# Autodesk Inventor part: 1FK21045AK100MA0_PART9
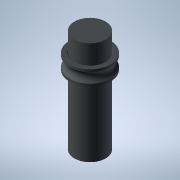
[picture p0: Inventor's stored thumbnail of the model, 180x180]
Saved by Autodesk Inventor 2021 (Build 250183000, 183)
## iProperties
Created: 2025-04
Part Number: 1FK21045AK100MA0_PART9
Material: Generic
Catalog Web Link: www.3dfindit.com
Description: -Servo synchronous motor
Document SubType Name: Modeling
Designer: psAdmin
Mass: 18.6788 g
Surface Area: 52.316 cm^2
Volume: 18.6788 cm^3
Density: 1 g/cm^3
Appearance: PSOLRGB-212-217-219
Category: PARTsolutions
Title: 1FK21045AK100MA0_PART9
Author: Cadenas PARTsolutions
Comments: Servo synchronous motor
Sending System: PARTsolutions
Preprocessor: ST-DEVELOPER v19.3
PSOL_IDENT_0: {$CADENAS_DATA/23d-libs/siemens_ag/_cat_/e0/5f/1fk21045ak100ma0.prj},213 {VTYP=3D},{NB=1FK21045AK100
PSOL_IDENT_1: MA0_PART9},{LINA=1FK21045AK100MA0_PART9},{NN=1FK21045AK100MA0_PART9},{NOPRJ=TRUE},{DATE=19.08.2025 1
PSOL_IDENT_2: 4:01:03},{GEOMDATE=30.07.2025 02:01:57},{VERSION=},{LINEID=10},{WBVAR=},{WBNUMERIC=}  {NB=1FK21045AK
PSOL_IDENT_3: 100MA0_PART9},{LINA=1FK21045AK100MA0_PART9},{KT=DUMMY},{PREVIEW=../../../_pool_/0f/2c/p_d211_xx_0043
PSOL_IDENT_4: 8j.png},{DESCSHORT=SIMOTICS S-1FK2 HD, SINAMICS S210 3AC 400V-480V, 1.7 Nm, 6000 rpm},{DESCLONG=SIMO
PSOL_IDENT_5: TICS S-1FK2 HD servo motor M0=2.4 Nm; PN = 1.07 kW at nN=6000 rpm (380-480 V); PN = 0.75 kW at nN=30
PSOL_IDENT_6: 00 rpm (200-240 V); with holding brake; degree of protection IP64; cylindrical shaft D19x40mm; absol
PSOL_IDENT_7: ute encoder 22-bit + 12-bit multiturn (encoder AM22DQC); with OCC interface; plug size M17, rotatabl
PSOL_IDENT_8: e; SIMOTICS S-1FK2 servomotorfor a wide range of uses in industrial environments. SIMOTICS S‑1FK2 se
PSOL_IDENT_9: rvomotors are compact synchronous motors with a high dynamic performance that set themselves apart a
PSOL_IDENT_10: s a result of their high power density, degree of protection and overload capability. The motors are
PSOL_IDENT_11: available in two variants: as High Dynamic variant (highest dynamic performance as a result of the
PSOL_IDENT_12: low intrinsic moment of inertia for applications demanding a high dynamic performance with low moved
PSOL_IDENT_13: masses) - and as Compact variant (precise and stable closed-loop control for medium up to large mov
PSOL_IDENT_14: ed masses as a result of a medium intrinsic moment of inertia). SIMOTICSS‑1FK2 servomotors fully exp
PSOL_IDENT_15: loit their strengths in a system with the SINAMICSS210 frequency converter and simple connection usi
PSOL_IDENT_16: ng the one cable connection (OCC). Advantages include the short control and positioning times, fast
PSOL_IDENT_17: and precise correction of disturbing quantities as well as stable control with a high dynamic perfor
PSOL_IDENT_18: mance. The servo motors can be configured to address a wide range of requirements. For example with
PSOL_IDENT_19: and without holding brake, IP64 or IP65 degree of protection, singleturn or multiturn absolute encod
PSOL_IDENT_20: ers - to name just a few. Further, the servomotors are available in different shaft heights extendin
PSOL_IDENT_21: g from 20 to 100. A shaft sealing ring is available to achieve an IP65 degree of protection and for
PSOL_IDENT_22: subsequent mounting at the motor or as spare part. SIMOTICS - the optimum motor for each and every m
PSOL_IDENT_23: otion control application.},{INTNO=804766807114},{SUPPLIERALTNO=1FK2104-5AK10-0MA0},{MANUID=1FK21045
PSOL_IDENT_24: AK100MA0},{MANUNAME=Siemens},{MANUTYPEDESC=Synchronous motor 1FK2-HD 2,39 Nm},{AAU732=SIMOTICS},{AAO
PSOL_IDENT_25: 057=S-1FK2},{AAU734=SIMOTICS S-1FK2 HD servo motor M0=2.4 Nm; PN = 1.07 kW at nN=6000 rpm (380-480 V
PSOL_IDENT_26: ); PN = 0.75 kW at nN=3000 rpm (200-240 V); with holding brake; degree of protection IP64; cylindric
PSOL_IDENT_27: al shaft D19x40mm; absolute encoder 22-bit + 12-bit multiturn (encoder AM22DQC); with OCC interface;
PSOL_IDENT_28: plug size M17, rotatable;},{AAW338=Synchronous motor 1FK2-HD 2,39 Nm},{AAO742=SIMOTICS},{AAO663=404
PSOL_IDENT_29: 2948691236},{NOCUPEROU=1},{PRICEQUANTITY=1},{QUANTITYMIN=1},{QUANTITYINT=1},{CTN=85015100},{COO=DE},
PSOL_IDENT_30: {AAO676=1FK2104-5AK10-0MA0},{AAO677=Siemens AG},{ORDERUNIT=C62},{CONTENTUNIT=C62}
NB: 1FK21045AK100MA0_PART9
NT: Servo synchronous motor
NBSYN: $MANUID._PART9
LINA: 1FK21045AK100MA0_PART9
CATALOG: SIEMENS
PREVIEW: ../../../_pool_/0f/2c/p_d211_xx_00438j.png
DESCSHORT: SIMOTICS S-1FK2 HD, SINAMICS S210 3AC 400V-480V, 1.7 Nm, 6000 rpm
DESCLONG: SIMOTICS S-1FK2 HD servo motor M0=2.4 Nm; PN = 1.07 kW at nN=6000 rpm (380-480 V); PN = 0.75 kW at nN=3000 rpm (200-240 V); with holding brake; degree of protec
INTNO: 804766807114
SUPPLIERALTNO: 1FK2104-5AK10-0MA0
MANUID: 1FK21045AK100MA0
MANUNAME: Siemens
MANUTYPEDESC: Synchronous motor 1FK2-HD 2,39 Nm
AAU732: SIMOTICS
AAO057: S-1FK2
AAU734: SIMOTICS S-1FK2 HD servo motor M0=2.4 Nm; PN = 1.07 kW at nN=6000 rpm (380-480 V); PN = 0.75 kW at nN=3000 rpm (200-240 V); with holding brake; degree of protec
AAW338: Synchronous motor 1FK2-HD 2,39 Nm
AAO742: SIMOTICS
AAO663: 4042948691236.0
NOCUPEROU: 1
PRICEQUANTITY: 1
QUANTITYMIN: 1
QUANTITYINT: 1
CTN: 85015100
COO: DE
ARTICLENO: 1FK21045AK100MA0_PART9
BOMINFO: 1FK21045AK100MA0_PART9
CREATOR: CADENAS GmbH
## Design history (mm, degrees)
feature "2025_04_17_15_45_15_0090"
body "Solid1"
